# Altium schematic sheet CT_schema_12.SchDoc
size 501 x 385 mm
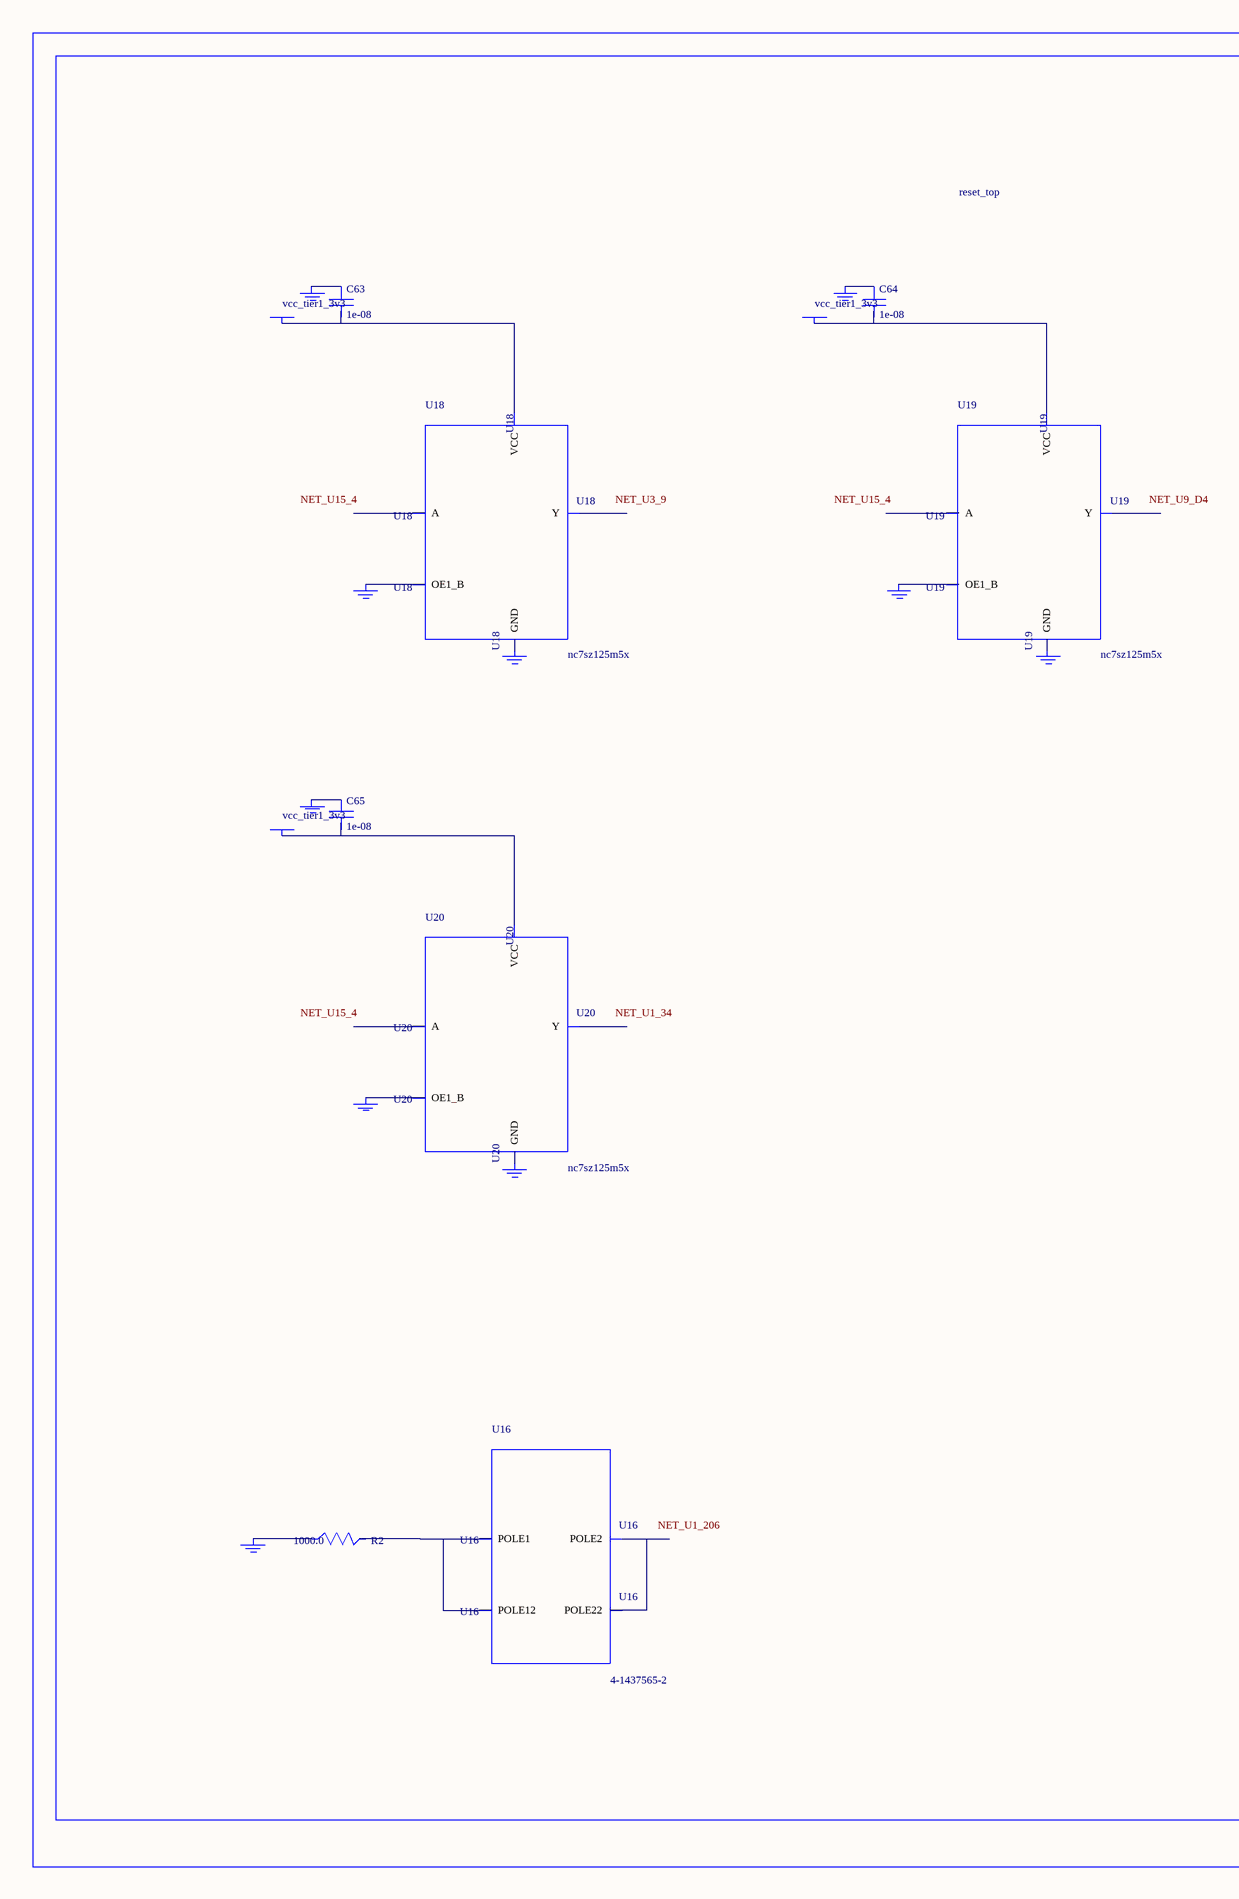
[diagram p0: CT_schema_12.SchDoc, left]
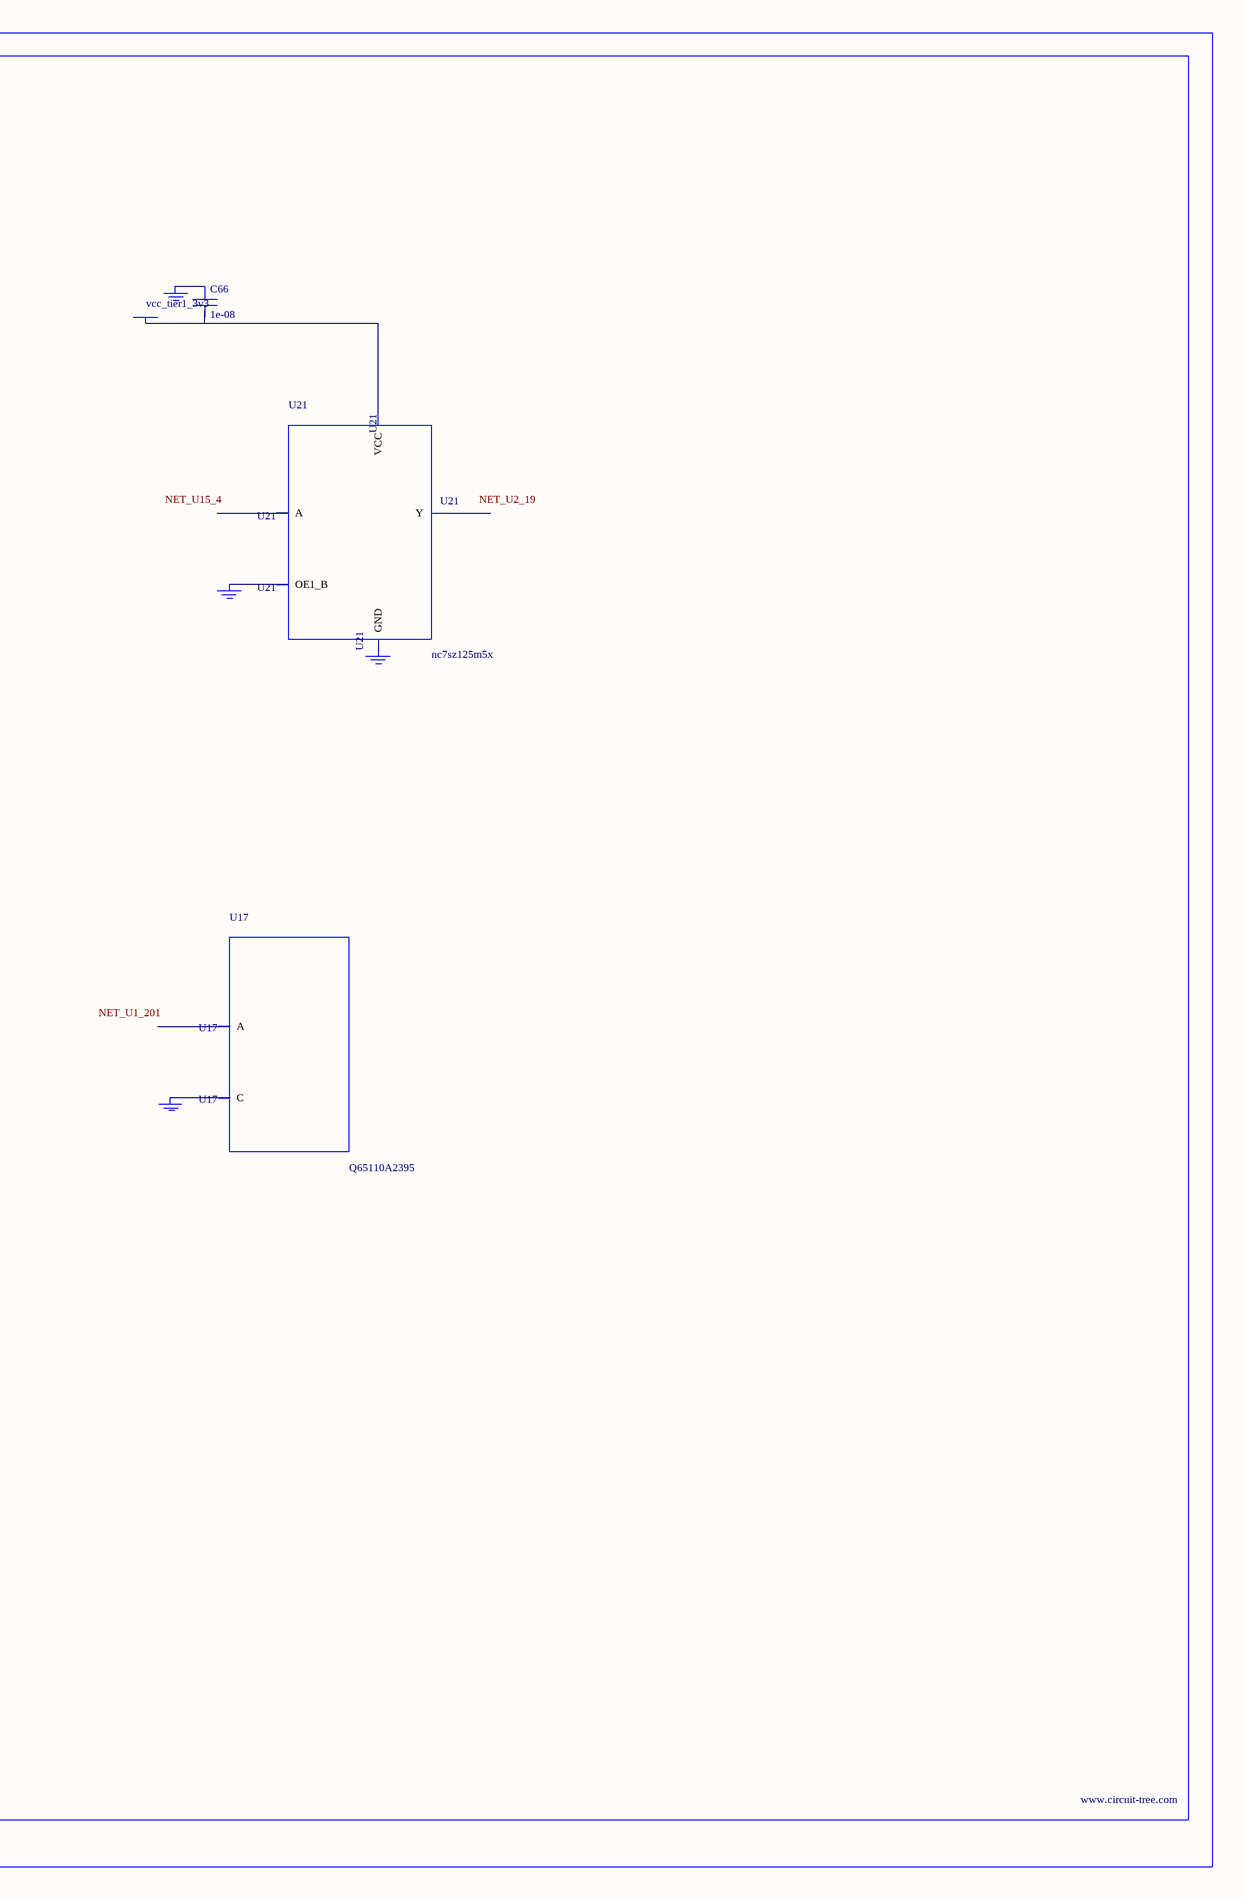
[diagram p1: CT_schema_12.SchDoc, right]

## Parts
BORDER11  (no value)
C63  1e-08  [C0402]
C64  1e-08  [C0402]
C65  1e-08  [C0402]
C66  1e-08  [C0402]
GND_INSTANCE_11_0  (no value)
GND_INSTANCE_11_1  (no value)
GND_INSTANCE_11_2  (no value)
GND_INSTANCE_11_3  (no value)
GND_INSTANCE_11_4  (no value)
GND_INSTANCE_11_5  (no value)
GND_INSTANCE_11_6  (no value)
GND_INSTANCE_11_7  (no value)
GND_INSTANCE_11_8  (no value)
GND_INSTANCE_11_9  (no value)
GND_INSTANCE_11_10  (no value)
GND_INSTANCE_11_11  (no value)
GND_INSTANCE_11_12  (no value)
GND_INSTANCE_11_13  (no value)
POWER_INSTANCE_11_0  vcc_tier1_3v3
POWER_INSTANCE_11_1  vcc_tier1_3v3
POWER_INSTANCE_11_2  vcc_tier1_3v3
POWER_INSTANCE_11_3  vcc_tier1_3v3
R2  1000.0  [R0603]
U16  4-1437565-2  [SW_4-1437565-2]
U17  Q65110A2395  [LGM67K-G1J2-24-Z]
U18  nc7sz125m5x  [NC7SZ125M5X]
U19  nc7sz125m5x  [NC7SZ125M5X]
U20  nc7sz125m5x  [NC7SZ125M5X]
U21  nc7sz125m5x  [NC7SZ125M5X]

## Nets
NetC63_1: C63.1 GND_INSTANCE_11_2.0(GND)
NetC63_2: C63.2 POWER_INSTANCE_11_0.0(PWR) U18.5(VCC)
NetC64_1: C64.1 GND_INSTANCE_11_5.0(GND)
NetC64_2: C64.2 POWER_INSTANCE_11_1.0(PWR) U19.5(VCC)
NetC65_1: C65.1 GND_INSTANCE_11_8.0(GND)
NetC65_2: C65.2 POWER_INSTANCE_11_2.0(PWR) U20.5(VCC)
NetC66_1: C66.1 GND_INSTANCE_11_11.0(GND)
NetC66_2: C66.2 POWER_INSTANCE_11_3.0(PWR) U21.5(VCC)
NetGND_INSTANCE_11_0_0: GND_INSTANCE_11_0.0(GND) R2.1
NetGND_INSTANCE_11_1_0: GND_INSTANCE_11_1.0(GND) U17.C
NetGND_INSTANCE_11_3_0: GND_INSTANCE_11_3.0(GND) U18.1(OE1_B)
NetGND_INSTANCE_11_4_0: GND_INSTANCE_11_4.0(GND) U18.3(GND)
NetGND_INSTANCE_11_6_0: GND_INSTANCE_11_6.0(GND) U19.1(OE1_B)
NetGND_INSTANCE_11_7_0: GND_INSTANCE_11_7.0(GND) U19.3(GND)
NetGND_INSTANCE_11_9_0: GND_INSTANCE_11_9.0(GND) U20.1(OE1_B)
NetGND_INSTANCE_11_10_0: GND_INSTANCE_11_10.0(GND) U20.3(GND)
NetGND_INSTANCE_11_12_0: GND_INSTANCE_11_12.0(GND) U21.1(OE1_B)
NetGND_INSTANCE_11_13_0: GND_INSTANCE_11_13.0(GND) U21.3(GND)
NetR2_2: R2.2 U16.1(POLE1) U16.2(POLE12)
NetU16_3: U16.3(POLE2) U16.4(POLE22)

Not connected (* = marked no-connect by the designer): U17 A; U18 2(A) 4(Y); U19 2(A) 4(Y); U20 2(A) 4(Y); U21 2(A) 4(Y)

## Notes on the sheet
- Labels drawn without touching a wire or pin: NET_U1_34, NET_U1_201, NET_U1_206, NET_U2_19, NET_U3_9, NET_U9_D4, NET_U15_4

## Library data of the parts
BORDER11 = BORDER_PAGE11
C63-C66 = C0402C103K3RAC
GND_INSTANCE_11_0-GND_INSTANCE_11_13 = GND
POWER_INSTANCE_11_0-POWER_INSTANCE_11_3 = PWR
R2 = RC0603JR-071KL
